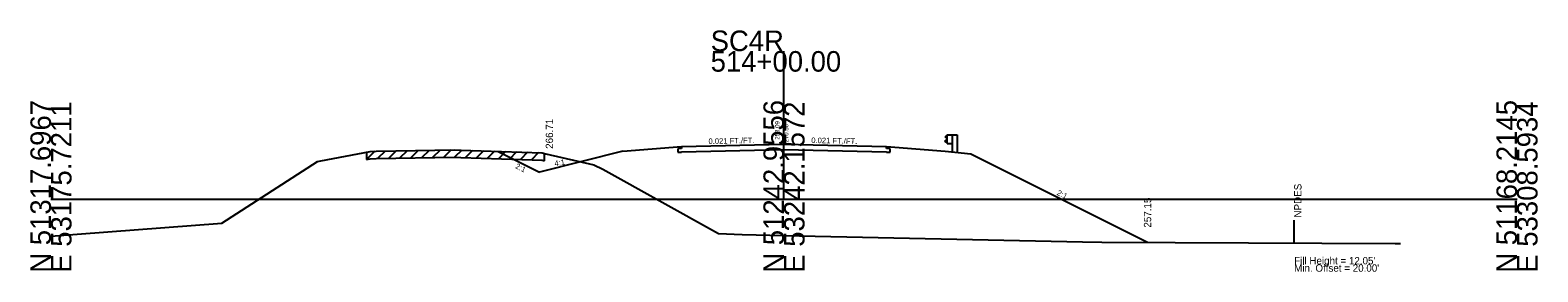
# Model space of a CAD drawing. Extents: x 7498 to 13027, y 90095 to 109625.
# Drawn here: x 8521.2 to 8726.8, y 104095.3 to 104128.2 of the extents above; entities that cross this region are included whole.
import ezdxf

# ---------------------------------------------------------------- set-up
doc = ezdxf.new("R2010")
doc.units = 0
for name, color, linetype in [('Level 10', 7, 'Continuous'), ('Level 11', 7, 'Continuous'), ('Level 12', 7, 'Continuous'), ('Level 24', 7, 'Continuous'), ('Level 32', 7, 'Continuous'), ('Level 33', 7, 'Continuous'), ('Level 50', 7, 'Continuous'), ('Level 55', 7, 'Continuous'), ('Level 59', 7, 'Continuous'), ('Level 6', 7, 'Continuous'), ('Level 60', 7, 'Continuous'), ('Level 61', 7, 'Continuous'), ('Level 63', 7, 'Continuous'), ('Level 7', 7, 'Continuous')]:
    doc.layers.add(name, color=color, linetype=linetype)

msp = doc.modelspace()

# ---------------------------------------------------------------- linework, layer by layer
at = {"layer": 'Level 11'}
for p, q in [((8609.99, 104112.07), (8609.49, 104112.05)), ((8609.49, 104112.05), (8609.49, 104111.57)), ((8609.99, 104112.37), (8609.99, 104112.07)), ((8637.99, 104112.07), (8637.99, 104112.37)), ((8638.49, 104112.05), (8637.99, 104112.07)), ((8638.49, 104111.57), (8638.49, 104112.05)), ((8609.49, 104111.57), (8609.99, 104111.59)), ((8637.99, 104111.59), (8638.49, 104111.57))]:
    msp.add_line(p, q, dxfattribs=at)
at = {"layer": 'Level 12'}
for p, q in [((8623.99, 104111.88), (8609.99, 104111.59)), ((8637.99, 104111.59), (8623.99, 104111.88))]:
    msp.add_line(p, q, dxfattribs=at)
at = {"layer": 'Level 24'}
for p, q in [((8646.26, 104112.78), (8646.26, 104113.95)), ((8646.26, 104113.95), (8646.93, 104113.95)), ((8646.93, 104113.95), (8646.93, 104111.6)), ((8646.93, 104113.95), (8647.6, 104113.95)), ((8647.6, 104113.95), (8647.6, 104111.54)), ((8646.26, 104113.88), (8645.99, 104113.68)), ((8645.99, 104113.68), (8645.99, 104113.63)), ((8645.99, 104113.63), (8646.26, 104113.43)), ((8645.99, 104113.1), (8646.26, 104113.3)), ((8645.99, 104113.05), (8645.99, 104113.1)), ((8646.26, 104112.85), (8645.99, 104113.05)), ((8646.26, 104112.78), (8646.93, 104112.78))]:
    msp.add_line(p, q, dxfattribs=at)
at = {"layer": 'Level 55'}
msp.add_line((8693.59, 104099.3), (8693.59, 104102.3), dxfattribs=at)
at = {"layer": 'Level 59'}
for p, q in [((8609.99, 104112.37), (8623.99, 104112.66)), ((8623.99, 104112.66), (8637.99, 104112.37))]:
    msp.add_line(p, q, dxfattribs=at)
at = {"layer": 'Level 6'}
for p, q in [((8601.99, 104111.7), (8609.99, 104112.37)), ((8637.99, 104112.37), (8645.99, 104111.7)), ((8645.99, 104111.7), (8649.49, 104111.35))]:
    msp.add_line(p, q, dxfattribs=at)
at = {"layer": 'Level 60'}
for p, q in [((8568.36, 104111.7), (8579.06, 104111.89)), ((8579.06, 104111.89), (8579.89, 104111.86)), ((8579.89, 104111.86), (8591.01, 104111.5)), ((8547.3, 104101.93), (8560.35, 104110.32)), ((8560.35, 104110.32), (8560.79, 104110.39)), ((8560.79, 104110.39), (8567.54, 104111.68)), ((8567.54, 104111.68), (8568.36, 104111.7)), ((8591.01, 104111.5), (8591.5, 104111.37)), ((8591.5, 104111.37), (8598.04, 104109.84)), ((8598.04, 104109.84), (8599.27, 104109.24)), ((8599.27, 104109.24), (8615.04, 104100.52)), ((8523.99, 104100.12), (8547.3, 104101.93)), ((8615.04, 104100.52), (8618.27, 104100.37)), ((8618.27, 104100.37), (8623.99, 104100.25)), ((8623.99, 104100.25), (8664.7, 104099.35)), ((8664.7, 104099.35), (8667.34, 104099.33)), ((8667.34, 104099.33), (8707.37, 104099.15)), ((8707.37, 104099.15), (8708.08, 104099.13))]:
    msp.add_line(p, q, dxfattribs=at)
at = {"layer": 'Level 61'}
for p, q in [((8577.07, 104111.85), (8576.05, 104110.83)), ((8578.57, 104111.88), (8577.55, 104110.86)), ((8580.02, 104111.85), (8579.05, 104110.88)), ((8568.16, 104111.7), (8567.05, 104110.59)), ((8567.05, 104111.59), (8567.05, 104110.59)), ((8567.05, 104110.59), (8567.54, 104110.68)), ((8567.54, 104110.68), (8568.36, 104110.7)), ((8568.36, 104110.7), (8579.06, 104110.88)), ((8569.57, 104111.72), (8568.55, 104110.7)), ((8571.07, 104111.75), (8570.05, 104110.73)), ((8572.57, 104111.77), (8571.55, 104110.75)), ((8574.07, 104111.8), (8573.05, 104110.78)), ((8575.57, 104111.82), (8574.55, 104110.81)), ((8579.06, 104110.88), (8579.89, 104110.86)), ((8579.89, 104110.86), (8591.01, 104110.5)), ((8581.52, 104111.81), (8580.55, 104110.84)), ((8583.02, 104111.76), (8582.05, 104110.79)), ((8584.52, 104111.71), (8583.55, 104110.74)), ((8586.02, 104111.66), (8585.05, 104110.69)), ((8587.52, 104111.61), (8586.55, 104110.64)), ((8589.02, 104111.56), (8588.05, 104110.59)), ((8590.52, 104111.51), (8589.55, 104110.54)), ((8591.01, 104110.5), (8591.32, 104110.41)), ((8591.32, 104110.41), (8591.32, 104111.41))]:
    msp.add_line(p, q, dxfattribs=at)
at = {"layer": 'Level 63'}
for p, q in [((8623.99, 104105.16), (8623.99, 104125.34)), ((8523.99, 104105.16), (8623.99, 104105.16)), ((8623.99, 104105.16), (8723.99, 104105.16))]:
    msp.add_line(p, q, dxfattribs=at)
at = {"layer": 'Level 7'}
for p, q in [((8584.99, 104111.69), (8590.65, 104108.86)), ((8601.99, 104111.7), (8590.65, 104108.86)), ((8649.49, 104111.35), (8673.59, 104099.3))]:
    msp.add_line(p, q, dxfattribs=at)

# ---------------------------------------------------------------- texts
at = {"layer": 'Level 10'}
msp.add_text('258.09', height=0.6, rotation=90, dxfattribs=at).set_placement((8623.37, 104113.27))
at = {"layer": 'Level 32'}
for s, rotation, p in [('0.021 FT./FT.', 1.1916, (8613.7, 104112.69)), ('0.021 FT./FT.', 358.8084, (8627.71, 104112.83)), ('2:1', 333.435, (8587.26, 104109.43)), ('4:1', 9.4623, (8592.74, 104109.65)), ('2:1', 333.435, (8661.14, 104105.8))]:
    msp.add_text(s, height=0.75, rotation=rotation, dxfattribs=at).set_placement(p)
at = {"layer": 'Level 33'}
for s, p in [('266.71', (8592.49, 104112.03)), ('257.15', (8674.09, 104101.3))]:
    msp.add_text(s, height=1, rotation=90, dxfattribs=at).set_placement(p)
at = {"layer": 'Level 50'}
msp.add_text(' NPDES', height=1, rotation=90, dxfattribs=at).set_placement((8694.59, 104102.3))
for s, p in [("Fill Height = 12.05' ", (8693.59, 104096.3)), ("Min. Offset = 20.00' ", (8693.59, 104095.3))]:
    msp.add_text(s, height=1, dxfattribs=at).set_placement(p)
at = {"layer": 'Level 59'}
msp.add_text(' 270.50', height=0.6, rotation=90, dxfattribs=at).set_placement((8624.59, 104112.66))
at = {"layer": 'Level 63'}
for s, p in [('SC4R', (8613.99, 104125.34)), ('514+00.00', (8613.99, 104122.54))]:
    msp.add_text(s, height=2.8, dxfattribs=at).set_placement(p)
for s, p in [('N 51317.6967', (8523.99, 104095.16)), ('E 53175.7211', (8526.79, 104095.16)), ('N 51242.9556', (8623.99, 104095.16)), ('E 53242.1572', (8626.79, 104095.16)), ('N 51168.2145', (8723.99, 104095.16)), ('E 53308.5934', (8726.79, 104095.16))]:
    msp.add_text(s, height=2.8, rotation=90, dxfattribs=at).set_placement(p)

doc.saveas('drawing.dxf')
